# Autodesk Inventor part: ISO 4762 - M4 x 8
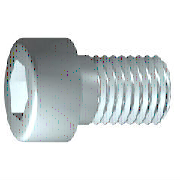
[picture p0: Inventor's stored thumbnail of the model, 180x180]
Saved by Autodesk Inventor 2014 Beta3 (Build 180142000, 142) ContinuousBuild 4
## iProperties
IsCustomPart: 0
Created: 2010-11
Part Number: ISO 4762 - M4 x 8
Material: Stainless Steel, 440C
Description: Hexagon Socket Head Cap Screw
Document SubType Name: Modeling
Standard: ISO 4762
Designer: Beta-8540w
Standard Revision: Fourth edition 2004-03-01
Standards Organization: ISO
Language: en-US
Size Designation: M4 x 8
Categories: <MemberInstance><Categories><Category DisplayName="Fasteners" InternalName="e4da775c-781d-43d5-af7c-5136215cf5a6" Mnemonic="FSTN"><Category DisplayName="Bolts"
Density: 7.75 g/cm^3
Appearance: Steel
Author: Beta-8540w
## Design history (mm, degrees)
sketch "Sketch1"
  geometry: L1 (-1, 0)-(8, 0); L2 (8, 0)-(8, 2); L3 (8, 2)-(1.75, 2); L4 (1.75, 2)-(1.32, 2); L5 (1.32, 2)-(0, 2); L6 (0, 2)-(0, 3.5); L7 (0, 3.5)-(-4, 3.5); L8 (-4, 3.5)-(-4, 1.732); L9 (-4, 1.732)-(-2, 1.732); L10 (-2, 1.732)-(-1, 0); L11 (-6.4, 0)-(10.4, 0) reference; L12 (0, -0.7)-(0, 4.2) reference; L13 (1.75, 2)-(0, 2)
  constraints: 22 end point, 6 parallel, 2 collinear, 2 perpendicular, 1 horizontal, 1 point on line
  dimensions: "d1" = 6.25 distance from line of L3.end L2 (= GEL); "d2" = 0.42952 distance of L4.end L3.end (computed from GAL); "d3" = 4 distance between parallel lines of L8 L6 (= KOH); "d4" = 2 distance of L8.end L9.end (= INTI); "d5" = 60 deg angle of L10 L1; "d6" = 4 diameter of L3 L1 (= GD); "d7" = 4 diameter of L5 L1 (= BDM); "d8" = 3.4641 diameter of L9 L1 (= 1.1547 x SW); "d9" = 7 diameter of L7 L1 (= KOD); "d26" = 8 distance between parallel lines of L12 L2 (= NLG)
revolve "Body" sketch "Sketch1" stored, may be unused: angle "d10" = 90 deg
sketch "Sketch2"
  geometry: L1 (0, -4.9)-(0, 4.9) reference; L2 (-4.9, 0)-(4.9, 0) reference; L3 (1.732, 0)-(0.866, -1.5); L4 (0.866, -1.5)-(-0.866, -1.5); L5 (-0.866, -1.5)-(-1.732, 0); L6 (-1.732, 0)-(-0.866, 1.5); L7 (-0.866, 1.5)-(0.866, 1.5); L8 (0.866, 1.5)-(1.732, 0); 2 further points
  constraints: 12 end point, 1 coincident, 1 horizontal alignment, 1 point on line, 12 other
extrude "Slot" join sketch "Sketch2" stored distance "d11" = 10; taper "d12" = 0 deg
workplane "Work Plane1"
fillet "Fillet2" dims "d30" = 0.1 (= R)
body "Solid1"
fillet "Fillet1" dims "d17" = 0.4 (= RR)
feature "Thread" dims "d13" = 6.25 (= GEL), "d14" = 0
chamfer "Chamfer1" distance "d15" = 0.42941 (= -0.5 x SPD + 0.5 x GD); stored, may be unused: second distance "d16" = 0.42941 (= GUL), angle "d27" = 45 deg
other parameters: "GD" = 4 [user parameter; used in 2 equation terms], "NLG" = 8 [user parameter; used in 1 equation term], "GEL" = 6.25 [user parameter; used in 2 equation terms], "KOD" = 7 [user parameter; used in 1 equation term], "KOH" = 4 [user parameter; used in 1 equation term], "INTI" = 2 [user parameter; used in 1 equation term], "GAL" = 0.42941 (= 0.61345 x PTC) [user parameter; used in 1 equation term], "GUL" = 0.42941 (= 0.61345 x PTC) [user parameter; used in 1 equation term], "BDM" = 4 (= NND) [user parameter; used in 1 equation term], "SW" = 3 [user parameter; used in 2 equation terms], "RR" = 0.4 [user parameter; used in 1 equation term], "SPD" = 3.14117 (= NND - 1.2269 x PTC) [user parameter; used in 1 equation term], "d19" = 0, "d28" = 0, "d29" = 0, "R" = 0.1 [user parameter; used in 1 equation term], "TOA" = 30 deg [user parameter], "GD1" = 3.14117 (= THREADDIA - 1.2269 x PTC) [user parameter], "THREADDIA" = 4 [user parameter; used in 1 equation term], "FAWI" = 45 deg [user parameter], "TPU" = 14.28571 (computed from PTC) [user parameter], "PTC" = 0.7 [user parameter; used in 5 equation terms], "NND" = 4 [user parameter; used in 2 equation terms], "E0" = 3.465 (= 1.155 x SW) [user parameter]
